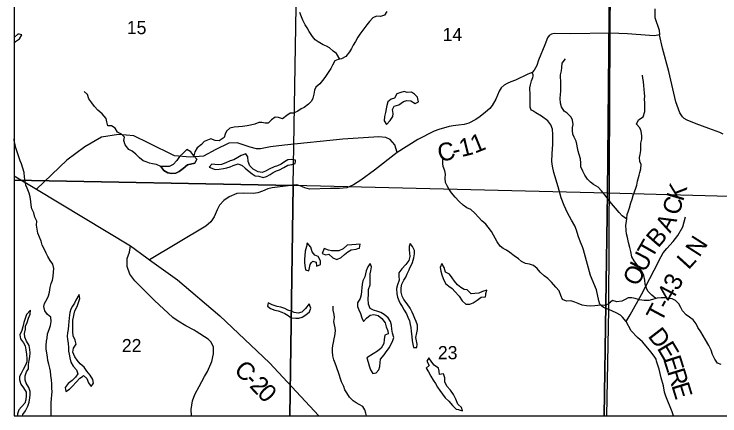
# Model space of a CAD drawing. Extents: x -452339 to 6403467, y -1 to 1814750.
# Drawn here: x -75201 to -63350, y 1547986 to 1554727 of the extents above; entities that cross this region are included whole.
import ezdxf

# ---------------------------------------------------------------- set-up
doc = ezdxf.new("R2010")
doc.units = 0
for name, color, linetype in [('Default', 7, 'Continuous'), ('GM_X_County', 7, 'Continuous'), ('GM_X_County_ROW', 7, 'Continuous'), ('GM_X_Major_Lake', 7, 'Continuous'), ('GM_X_Major_Lake_Text', 7, 'Continuous'), ('GM_X_Major_River_Text', 7, 'Continuous'), ('GM_X_Section', 7, 'Continuous'), ('GM_X_Section_Text', 7, 'Continuous'), ('GM_X_Township_Road_Text', 7, 'Continuous'), ('GM_X_Unincorporated_Location', 7, 'Continuous')]:
    doc.layers.add(name, color=color, linetype=linetype)

msp = doc.modelspace()

# ---------------------------------------------------------------- linework, layer by layer
at = {"layer": 'Default'}
msp.add_lwpolyline([(-68770, 1552404), (-68810, 1552533), (-68887, 1552621), (-68957, 1552656), (-69077, 1552667), (-69679, 1552627), (-70661, 1552529), (-70894, 1552499), (-71064, 1552465), (-71130, 1552465), (-71236, 1552494), (-71457, 1552569), (-71597, 1552563), (-71812, 1552458), (-72022, 1552346), (-72245, 1552325), (-72507, 1552350), (-72940, 1552559), (-73190, 1552686), (-73448, 1552709), (-73731, 1552664), (-74015, 1552500), (-74314, 1552276), (-74826, 1551789)], dxfattribs=at)
at = {"layer": 'GM_X_County_ROW'}
for points in [[(-63293, 1552711), (-63353, 1552739), (-63537, 1552806), (-63750, 1552884), (-63900, 1552947), (-63952, 1552973), (-63980, 1553002), (-64023, 1553072), (-64090, 1553258), (-64209, 1553766), (-64311, 1554154), (-64363, 1554377)], [(-65303, 1549803), (-65305, 1549804), (-65338, 1549832), (-65365, 1549862), (-65383, 1549916), (-65420, 1550101), (-65525, 1550340), (-65642, 1550774), (-65658, 1550824), (-65693, 1550898), (-65728, 1551006), (-65760, 1551103), (-65787, 1551175), (-65839, 1551271), (-65906, 1551395), (-65967, 1551518), (-66014, 1551642), (-66063, 1551830), (-66139, 1552068), (-66162, 1552176), (-66170, 1552254), (-66165, 1552380), (-66156, 1552543), (-66153, 1552709), (-66158, 1552797), (-66187, 1552871), (-66237, 1552939), (-66344, 1553016), (-66438, 1553073), (-66492, 1553103), (-66516, 1553117), (-66526, 1553131), (-66534, 1553165), (-66534, 1553369), (-66539, 1553491), (-66531, 1553543), (-66516, 1553607), (-66490, 1553662), (-66484, 1553688), (-66484, 1553708), (-66502, 1553748)], [(-64921, 1549570), (-64855, 1549683), (-64665, 1550021), (-64454, 1550431), (-64334, 1550658), (-64302, 1550724), (-64241, 1550793), (-64134, 1550910), (-64056, 1551013), (-63973, 1551160), (-63927, 1551324)], [(-72004, 1548644), (-72003, 1548644), (-71956, 1548730), (-71880, 1548900), (-71854, 1549028), (-71854, 1549136), (-71892, 1549222), (-71943, 1549273), (-72143, 1549403), (-72177, 1549425), (-72316, 1549498), (-72444, 1549574), (-72537, 1549638), (-72843, 1549921), (-73174, 1550252), (-73257, 1550363), (-73305, 1550495), (-73302, 1550627), (-73265, 1550732), (-73249, 1550837)], [(-64127, 1547986), (-64153, 1548052), (-64257, 1548317), (-64280, 1548385), (-64296, 1548487), (-64335, 1548625), (-64370, 1548769), (-64415, 1548903), (-64422, 1548937), (-64444, 1548973), (-64506, 1549054), (-64651, 1549227), (-64734, 1549301), (-64839, 1549410), (-64921, 1549570), (-64984, 1549644), (-65018, 1549673), (-65093, 1549716), (-65216, 1549772), (-65260, 1549790), (-65303, 1549803)], [(-72225, 1547986), (-72226, 1548093), (-72207, 1548239), (-72165, 1548344), (-72096, 1548479), (-72004, 1548644)]]:
    msp.add_lwpolyline(points, dxfattribs=at)
at = {"layer": 'GM_X_Major_River_Text'}
for points in [[(-75118, 1554388), (-75137, 1554390), (-75201, 1554333)], [(-75201, 1554251), (-75176, 1554266), (-75112, 1554314), (-75069, 1554382), (-75118, 1554388)], [(-68422, 1553307), (-68428, 1553333), (-68478, 1553385), (-68530, 1553416), (-68600, 1553412), (-68650, 1553426), (-68710, 1553414), (-68772, 1553388), (-68815, 1553319), (-68871, 1553301), (-68927, 1553253), (-68941, 1553193), (-68953, 1553139), (-68967, 1553075), (-68982, 1553008), (-68990, 1552934), (-68948, 1552876)], [(-68948, 1552876), (-68888, 1552943), (-68841, 1553009), (-68837, 1553061), (-68847, 1553125), (-68817, 1553183), (-68743, 1553207), (-68663, 1553262), (-68607, 1553280), (-68537, 1553270), (-68465, 1553230), (-68411, 1553257), (-68422, 1553307)], [(-72182, 1552348), (-72231, 1552417), (-72300, 1552453), (-72365, 1552396), (-72423, 1552338), (-72466, 1552269), (-72530, 1552205), (-72595, 1552170), (-72740, 1552171)], [(-70476, 1552255), (-70474, 1552274), (-70544, 1552286), (-70604, 1552284), (-70659, 1552248), (-70719, 1552210), (-70779, 1552179), (-70835, 1552163), (-70917, 1552127), (-70979, 1552093), (-71035, 1552070), (-71105, 1552080), (-71185, 1552128), (-71245, 1552184), (-71271, 1552254), (-71277, 1552330), (-71310, 1552382), (-71388, 1552357), (-71447, 1552321), (-71511, 1552283), (-71573, 1552265), (-71647, 1552234), (-71717, 1552206), (-71773, 1552200), (-71829, 1552204), (-71879, 1552212), (-71927, 1552161)], [(-72740, 1552171), (-72685, 1552104), (-72619, 1552062), (-72553, 1552055), (-72483, 1552061), (-72431, 1552086), (-72362, 1552138), (-72288, 1552197), (-72167, 1552226), (-72135, 1552292), (-72182, 1552348)], [(-71927, 1552161), (-71823, 1552122), (-71757, 1552128), (-71687, 1552138), (-71629, 1552148), (-71575, 1552163), (-71521, 1552185), (-71437, 1552213), (-71369, 1552187), (-71319, 1552145), (-71253, 1552084), (-71201, 1552048), (-71151, 1552016), (-71091, 1552008), (-71017, 1551988), (-70965, 1552002), (-70903, 1552035), (-70851, 1552071), (-70797, 1552095), (-70745, 1552117), (-70671, 1552154), (-70603, 1552194), (-70535, 1552206), (-70481, 1552220), (-70476, 1552255)], [(-70280, 1550888), (-70293, 1550826), (-70311, 1550750), (-70321, 1550675), (-70325, 1550613), (-70325, 1550561), (-70318, 1550511), (-70306, 1550439), (-70254, 1550421), (-70240, 1550472), (-70232, 1550524), (-70205, 1550560)], [(-70205, 1550560), (-70187, 1550584), (-70131, 1550566), (-70122, 1550498), (-70059, 1550526), (-70057, 1550588), (-70095, 1550658), (-70149, 1550684), (-70199, 1550738), (-70217, 1550814), (-70280, 1550888)], [(-69431, 1550792), (-69404, 1550801), (-69390, 1550867), (-69458, 1550863), (-69528, 1550856), (-69606, 1550848), (-69675, 1550788), (-69749, 1550756), (-69803, 1550753), (-69871, 1550757), (-69923, 1550767), (-69995, 1550795)], [(-68554, 1550469), (-68535, 1550507), (-68513, 1550558), (-68487, 1550638), (-68478, 1550704), (-68480, 1550762), (-68512, 1550828), (-68548, 1550880), (-68570, 1550826), (-68568, 1550770), (-68560, 1550718), (-68554, 1550660), (-68573, 1550595), (-68623, 1550523), (-68691, 1550455), (-68743, 1550385), (-68742, 1550329), (-68736, 1550265), (-68762, 1550186), (-68782, 1550122), (-68774, 1550034), (-68761, 1549976), (-68743, 1549924), (-68717, 1549872), (-68685, 1549820), (-68651, 1549760), (-68613, 1549698), (-68590, 1549643), (-68562, 1549581), (-68548, 1549521), (-68540, 1549471), (-68532, 1549399), (-68522, 1549320), (-68515, 1549244), (-68497, 1549132)], [(-69995, 1550795), (-70031, 1550712), (-69969, 1550689), (-69915, 1550701), (-69851, 1550637), (-69781, 1550611), (-69707, 1550646), (-69651, 1550692), (-69597, 1550740), (-69541, 1550774), (-69458, 1550785), (-69431, 1550792)], [(-69252, 1550501), (-69263, 1550487), (-69287, 1550421), (-69298, 1550371), (-69314, 1550317), (-69346, 1550254), (-69358, 1550198), (-69364, 1550134), (-69367, 1550076), (-69373, 1550014), (-69393, 1549956), (-69435, 1549884), (-69437, 1549822), (-69410, 1549764), (-69382, 1549702), (-69364, 1549632), (-69336, 1549570), (-69284, 1549626), (-69220, 1549678), (-69160, 1549687), (-69086, 1549671), (-69024, 1549617), (-68972, 1549547), (-68956, 1549479), (-68928, 1549415), (-68919, 1549363), (-68975, 1549339), (-68985, 1549267), (-68993, 1549199), (-69037, 1549123), (-69101, 1549070), (-69170, 1549024), (-69278, 1548960)], [(-69278, 1548960), (-69254, 1548886), (-69238, 1548828), (-69218, 1548758), (-69179, 1548698), (-69119, 1548710), (-69074, 1548760), (-69062, 1548812), (-69056, 1548882), (-69048, 1548936), (-68986, 1549009), (-68955, 1549063), (-68899, 1549131), (-68875, 1549181), (-68847, 1549233), (-68827, 1549301), (-68848, 1549373), (-68858, 1549439), (-68864, 1549507), (-68880, 1549567), (-68922, 1549633), (-68990, 1549687), (-69041, 1549719), (-69093, 1549737), (-69167, 1549759), (-69221, 1549790), (-69251, 1549862), (-69255, 1549952), (-69249, 1550021), (-69250, 1550109), (-69224, 1550183), (-69220, 1550245), (-69220, 1550367), (-69213, 1550419), (-69199, 1550487), (-69221, 1550541), (-69252, 1550501)], [(-68497, 1549132), (-68437, 1549133), (-68431, 1549189), (-68447, 1549247), (-68456, 1549303), (-68438, 1549377), (-68426, 1549437), (-68430, 1549505), (-68452, 1549567), (-68474, 1549619), (-68495, 1549673), (-68517, 1549727), (-68551, 1549793), (-68603, 1549867), (-68659, 1549939), (-68687, 1549996), (-68704, 1550060), (-68704, 1550133), (-68688, 1550193), (-68656, 1550265), (-68624, 1550315), (-68601, 1550369), (-68569, 1550439), (-68554, 1550469)], [(-68017, 1550541), (-68047, 1550473), (-68037, 1550415), (-68017, 1550351), (-67999, 1550291), (-67956, 1550209), (-67902, 1550165), (-67848, 1550124), (-67800, 1550070), (-67730, 1549992), (-67678, 1549916), (-67618, 1549860), (-67550, 1549860), (-67494, 1549881), (-67428, 1549929), (-67356, 1549975), (-67284, 1549985), (-67282, 1550014)], [(-67282, 1550014), (-67280, 1550037), (-67266, 1550093), (-67336, 1550075), (-67400, 1550043), (-67466, 1550041), (-67524, 1550033), (-67592, 1550098), (-67644, 1550104), (-67700, 1550142), (-67756, 1550184), (-67807, 1550248), (-67845, 1550302), (-67891, 1550364), (-67955, 1550399), (-67979, 1550473), (-68017, 1550541)], [(-74108, 1550025), (-74165, 1549930), (-74187, 1549878), (-74218, 1549828), (-74248, 1549774), (-74265, 1549722), (-74275, 1549630), (-74280, 1549562), (-74286, 1549505), (-74295, 1549435), (-74305, 1549377), (-74309, 1549321), (-74304, 1549269), (-74296, 1549207), (-74289, 1549127), (-74285, 1549073), (-74277, 1549019), (-74266, 1548959), (-74248, 1548886), (-74207, 1548822), (-74151, 1548760), (-74130, 1548692), (-74172, 1548634), (-74228, 1548582), (-74295, 1548527), (-74341, 1548461), (-74330, 1548397), (-74272, 1548433), (-74221, 1548482), (-74159, 1548550), (-74096, 1548616), (-74055, 1548647)], [(-74055, 1548647), (-74034, 1548663), (-73982, 1548615), (-73952, 1548541), (-73907, 1548480), (-73868, 1548536), (-73878, 1548598), (-73925, 1548670), (-73979, 1548737), (-74023, 1548801), (-74092, 1548857), (-74142, 1548918), (-74182, 1548978), (-74215, 1549052), (-74205, 1549120), (-74158, 1549188), (-74178, 1549258), (-74209, 1549330), (-74213, 1549404), (-74216, 1549468), (-74216, 1549540), (-74213, 1549590), (-74205, 1549642), (-74193, 1549698), (-74180, 1549750), (-74142, 1549819), (-74119, 1549889), (-74099, 1549957), (-74108, 1550025)], [(-70934, 1549883), (-70948, 1549829), (-70898, 1549787), (-70824, 1549759), (-70766, 1549749), (-70704, 1549727), (-70654, 1549701), (-70600, 1549668), (-70573, 1549650)], [(-70573, 1549650), (-70544, 1549630), (-70470, 1549624), (-70418, 1549628), (-70366, 1549640), (-70300, 1549681), (-70242, 1549733), (-70218, 1549795), (-70246, 1549863), (-70310, 1549789), (-70368, 1549726), (-70430, 1549708), (-70500, 1549722), (-70550, 1549742), (-70604, 1549762), (-70656, 1549786), (-70722, 1549811), (-70784, 1549821), (-70866, 1549851), (-70934, 1549883)], [(-74925, 1549757), (-74992, 1549687), (-75016, 1549622), (-75037, 1549554), (-75053, 1549482), (-75074, 1549416), (-75103, 1549348), (-75095, 1549278), (-75041, 1549212), (-75016, 1549160), (-75002, 1549096), (-74993, 1549022), (-74989, 1548944), (-74990, 1548890), (-75008, 1548836), (-75050, 1548762), (-75085, 1548696), (-75109, 1548645), (-75110, 1548593), (-75088, 1548518), (-75043, 1548454), (-74999, 1548382), (-75001, 1548326), (-75004, 1548254), (-75022, 1548200), (-75075, 1548135), (-75123, 1548085), (-75146, 1548019), (-75146, 1547986)], [(-75058, 1547986), (-75052, 1548008), (-75007, 1548068), (-74969, 1548148), (-74946, 1548216), (-74936, 1548286), (-74933, 1548341), (-74933, 1548395), (-74952, 1548464), (-75000, 1548534), (-75016, 1548586), (-75017, 1548658), (-74991, 1548724), (-74960, 1548774), (-74958, 1548845), (-74949, 1548917), (-74937, 1548977), (-74932, 1549041), (-74936, 1549097), (-74949, 1549169), (-74993, 1549238), (-75023, 1549304), (-75026, 1549368), (-75012, 1549440), (-75009, 1549490), (-74983, 1549555), (-74960, 1549623), (-74932, 1549693), (-74925, 1549757)], [(-67740, 1548091), (-67728, 1548088), (-67674, 1548072), (-67690, 1548124), (-67750, 1548180), (-67785, 1548264), (-67825, 1548342), (-67873, 1548416), (-67935, 1548482), (-67969, 1548558), (-67968, 1548622), (-67990, 1548690), (-68060, 1548678), (-68064, 1548734), (-68076, 1548788), (-68150, 1548835), (-68186, 1548889), (-68235, 1548959), (-68272, 1548905), (-68233, 1548829), (-68284, 1548787)], [(-68284, 1548787), (-68244, 1548723), (-68204, 1548651), (-68163, 1548587), (-68127, 1548529), (-68091, 1548465), (-68053, 1548413), (-68009, 1548351), (-67963, 1548288), (-67903, 1548232), (-67842, 1548160), (-67780, 1548100), (-67740, 1548091)]]:
    msp.add_lwpolyline(points, dxfattribs=at)
at = {"layer": 'GM_X_Section'}
for points in [[(-64444, 1554816), (-64441, 1554672), (-64370, 1554460), (-64363, 1554377), (-64448, 1554362), (-64530, 1554371), (-64899, 1554399), (-65190, 1554407), (-65211, 1554407)], [(-65211, 1554407), (-65855, 1554399), (-66135, 1554402), (-66177, 1554392), (-66217, 1554368), (-66247, 1554330), (-66292, 1554214), (-66396, 1553957), (-66424, 1553863), (-66466, 1553787), (-66502, 1553748), (-66576, 1553718), (-66782, 1553620), (-66858, 1553590), (-66924, 1553564), (-66972, 1553533), (-67020, 1553489), (-67054, 1553437), (-67111, 1553299), (-67175, 1553195), (-67215, 1553144), (-67285, 1553080), (-67373, 1553012), (-67449, 1552958), (-67567, 1552900), (-67643, 1552873), (-67741, 1552863), (-67829, 1552855), (-67895, 1552839), (-68067, 1552791), (-68145, 1552763), (-68424, 1552624), (-68770, 1552404), (-69150, 1552108), (-69377, 1551940), (-69501, 1551863), (-69613, 1551815), (-69739, 1551803), (-69891, 1551803), (-70241, 1551792), (-70317, 1551812), (-70397, 1551848), (-70459, 1551862), (-70555, 1551852), (-70867, 1551815), (-70939, 1551795), (-71029, 1551759), (-71111, 1551729), (-71185, 1551717), (-71353, 1551722), (-71463, 1551716), (-71592, 1551660), (-71682, 1551598), (-71750, 1551519), (-71794, 1551441), (-71844, 1551325), (-71900, 1551239), (-71980, 1551169), (-72928, 1550606)], [(-75201, 1552016), (-74826, 1551789), (-73249, 1550837), (-72974, 1550639)], [(-72974, 1550639), (-72974, 1550639), (-72928, 1550606), (-72455, 1550267), (-71749, 1549667), (-70915, 1548873), (-70085, 1547986)]]:
    msp.add_lwpolyline(points, dxfattribs=at)
at = {"layer": 'GM_X_Section_Text'}
msp.add_lwpolyline([(-65017, 1563141), (-75201, 1563141), (-75201, 1547986), (-65250, 1547986), (-65216, 1549772), (-65190, 1554407), (-65173, 1556707), (-65039, 1562427)], close=True, dxfattribs=at)
at = {"layer": 'GM_X_Township_Road_Text'}
for points in [[(-68940, 1554773), (-68980, 1554710), (-69048, 1554690), (-69118, 1554692), (-69175, 1554666), (-69235, 1554603), (-69279, 1554545), (-69347, 1554459), (-69397, 1554393), (-69432, 1554340), (-69466, 1554270), (-69506, 1554206), (-69538, 1554150), (-69572, 1554094), (-69631, 1554017), (-69701, 1553977), (-69757, 1553967), (-69817, 1553945), (-69855, 1553872), (-69885, 1553816), (-69926, 1553746), (-69982, 1553666), (-70022, 1553613), (-70070, 1553559), (-70135, 1553503), (-70157, 1553453), (-70169, 1553385), (-70183, 1553315), (-70209, 1553264), (-70255, 1553214), (-70328, 1553162), (-70382, 1553136), (-70438, 1553101), (-70508, 1553067), (-70566, 1553063), (-70622, 1553025), (-70694, 1552972), (-70764, 1552994), (-70816, 1553000), (-70878, 1552956), (-70933, 1552900), (-70987, 1552897), (-71041, 1552911), (-71093, 1552911), (-71161, 1552879), (-71229, 1552866), (-71287, 1552852), (-71367, 1552842), (-71431, 1552836), (-71507, 1552829), (-71577, 1552815), (-71635, 1552763), (-71656, 1552713), (-71672, 1552657), (-71756, 1552600), (-71826, 1552608), (-71896, 1552632), (-72011, 1552588)], [(-69732, 1553971), (-69789, 1554065), (-69843, 1554105), (-69904, 1554163), (-69958, 1554188), (-70010, 1554212), (-70096, 1554260), (-70146, 1554296), (-70192, 1554354), (-70244, 1554436), (-70282, 1554496), (-70315, 1554550), (-70355, 1554626), (-70373, 1554680), (-70403, 1554756)], [(-64914, 1551289), (-64989, 1551341), (-65039, 1551400), (-65103, 1551472), (-65170, 1551548), (-65228, 1551622), (-65284, 1551692), (-65338, 1551764), (-65392, 1551824), (-65470, 1551869), (-65521, 1551905), (-65573, 1551959), (-65619, 1552025), (-65653, 1552091), (-65685, 1552167), (-65685, 1552227), (-65688, 1552297), (-65712, 1552369), (-65732, 1552425), (-65740, 1552483), (-65750, 1552545), (-65765, 1552597), (-65799, 1552661), (-65817, 1552715), (-65825, 1552773), (-65825, 1552823), (-65815, 1552875), (-65826, 1552945), (-65850, 1552999), (-65912, 1553065), (-65962, 1553101), (-66012, 1553171), (-66024, 1553231), (-66033, 1553313), (-66027, 1553377), (-66021, 1553435), (-66021, 1553605), (-66024, 1553661), (-66028, 1553711), (-66010, 1553774), (-66006, 1553830), (-66000, 1553902), (-65943, 1553978)], [(-64428, 1549953), (-64491, 1550013), (-64561, 1550079), (-64582, 1550131), (-64602, 1550197), (-64612, 1550263), (-64626, 1550339), (-64654, 1550405), (-64701, 1550469), (-64743, 1550525), (-64787, 1550585), (-64831, 1550656), (-64847, 1550742), (-64864, 1550812), (-64886, 1550894), (-64902, 1550977), (-64916, 1551039), (-64926, 1551099), (-64929, 1551183), (-64917, 1551249), (-64913, 1551299), (-64905, 1551363), (-64885, 1551427), (-64868, 1551477), (-64844, 1551559), (-64824, 1551623), (-64804, 1551682), (-64782, 1551744), (-64759, 1551806), (-64743, 1551856), (-64735, 1551924), (-64707, 1552022), (-64695, 1552072), (-64678, 1552130), (-64672, 1552201), (-64696, 1552254), (-64702, 1552319), (-64690, 1552373), (-64676, 1552439), (-64677, 1552493), (-64675, 1552563), (-64663, 1552627), (-64663, 1552685), (-64671, 1552761), (-64696, 1552817), (-64752, 1552883), (-64714, 1552951), (-64636, 1553006), (-64613, 1553094), (-64613, 1553156), (-64611, 1553238), (-64615, 1553298), (-64613, 1553352), (-64615, 1553402), (-64622, 1553466), (-64626, 1553522), (-64630, 1553594), (-64642, 1553650), (-64650, 1553702)], [(-72011, 1552588), (-72057, 1552539), (-72125, 1552481), (-72164, 1552414), (-72182, 1552348), (-72135, 1552292), (-72167, 1552226), (-72219, 1552216), (-72288, 1552197), (-72362, 1552138), (-72431, 1552086), (-72483, 1552061), (-72553, 1552055), (-72619, 1552062), (-72685, 1552104), (-72740, 1552171), (-72810, 1552201), (-72876, 1552216), (-72930, 1552228), (-72984, 1552247), (-73034, 1552265), (-73098, 1552314), (-73159, 1552376), (-73221, 1552430), (-73275, 1552457), (-73334, 1552531), (-73358, 1552609), (-73345, 1552661), (-73397, 1552712), (-73465, 1552748), (-73502, 1552812), (-73564, 1552851), (-73630, 1552855), (-73643, 1552917), (-73657, 1552976), (-73722, 1553054), (-73794, 1553113), (-73849, 1553175), (-73895, 1553241), (-73945, 1553306), (-73968, 1553376), (-74024, 1553430)], [(-74655, 1549237), (-74647, 1549291), (-74638, 1549362), (-74614, 1549434), (-74589, 1549504), (-74577, 1549570), (-74584, 1549642), (-74642, 1549686), (-74683, 1549747), (-74703, 1549823), (-74688, 1549874), (-74648, 1549950), (-74625, 1550002), (-74609, 1550062), (-74594, 1550140), (-74576, 1550207), (-74557, 1550261), (-74543, 1550325), (-74538, 1550395), (-74532, 1550457), (-74553, 1550531), (-74593, 1550591), (-74636, 1550659), (-74662, 1550714), (-74693, 1550780), (-74731, 1550848), (-74744, 1550916), (-74776, 1550982), (-74803, 1551049), (-74813, 1551117), (-74824, 1551187), (-74822, 1551253), (-74851, 1551319), (-74869, 1551391), (-74904, 1551461), (-74912, 1551521), (-74923, 1551585), (-74931, 1551659), (-74948, 1551721), (-74983, 1551807), (-75005, 1551858), (-75028, 1551990), (-75033, 1552070), (-75053, 1552142), (-75076, 1552214), (-75100, 1552268), (-75129, 1552348), (-75147, 1552414), (-75170, 1552482), (-75184, 1552534), (-75199, 1552610), (-75201, 1552633)], [(-64007, 1549805), (-64037, 1549863), (-64097, 1549924), (-64149, 1549948), (-64203, 1549956), (-64267, 1549968), (-64335, 1549968), (-64401, 1549961), (-64479, 1549937), (-64545, 1549923), (-64623, 1549921), (-64697, 1549934), (-64775, 1549958), (-64827, 1549968), (-64891, 1549964), (-64943, 1549941), (-64995, 1549913), (-65079, 1549901), (-65151, 1549921), (-65225, 1549862), (-65280, 1549836), (-65334, 1549846), (-65398, 1549838), (-65452, 1549834), (-65520, 1549827), (-65590, 1549833), (-65660, 1549843), (-65732, 1549871), (-65784, 1549896), (-65852, 1549914), (-65924, 1549908), (-65990, 1549940), (-66021, 1550006), (-66049, 1550084), (-66103, 1550144), (-66175, 1550229), (-66241, 1550289), (-66299, 1550335), (-66370, 1550395), (-66420, 1550461), (-66478, 1550507), (-66548, 1550530), (-66614, 1550544), (-66680, 1550578), (-66732, 1550622), (-66802, 1550672), (-66876, 1550725), (-66933, 1550765), (-66991, 1550793), (-67041, 1550833), (-67087, 1550907), (-67121, 1550965), (-67151, 1551017), (-67187, 1551079), (-67240, 1551151), (-67280, 1551202), (-67350, 1551256), (-67402, 1551318), (-67464, 1551386), (-67534, 1551446), (-67600, 1551478), (-67662, 1551519), (-67727, 1551581), (-67797, 1551657), (-67855, 1551731), (-67899, 1551793), (-67931, 1551845), (-67958, 1551903), (-67962, 1551975), (-67958, 1552043), (-67968, 1552099), (-67996, 1552169), (-68004, 1552221), (-68003, 1552285)], [(-69283, 1547986), (-69295, 1548031), (-69314, 1548087), (-69346, 1548143), (-69406, 1548179), (-69456, 1548202), (-69508, 1548238), (-69568, 1548302), (-69614, 1548370), (-69646, 1548422), (-69665, 1548478), (-69705, 1548556), (-69723, 1548608), (-69745, 1548682), (-69789, 1548806), (-69812, 1548870), (-69830, 1548926), (-69848, 1548992), (-69856, 1549064), (-69852, 1549114), (-69847, 1549164), (-69839, 1549216), (-69827, 1549280), (-69815, 1549330), (-69805, 1549412), (-69809, 1549462), (-69822, 1549512), (-69830, 1549572), (-69820, 1549638), (-69824, 1549688), (-69844, 1549760), (-69844, 1549824)], [(-63330, 1548846), (-63392, 1548872), (-63436, 1548940), (-63475, 1549016), (-63497, 1549088), (-63537, 1549164), (-63589, 1549260), (-63630, 1549327), (-63672, 1549397), (-63718, 1549467), (-63748, 1549531), (-63798, 1549599), (-63862, 1549643), (-63916, 1549681), (-63975, 1549747), (-64007, 1549805)], [(-74580, 1547986), (-74579, 1548047), (-74580, 1548103), (-74578, 1548155), (-74576, 1548205), (-74571, 1548279), (-74565, 1548333), (-74562, 1548392), (-74566, 1548446), (-74567, 1548526), (-74575, 1548590), (-74582, 1548662), (-74591, 1548734), (-74603, 1548789), (-74620, 1548851), (-74636, 1548917), (-74640, 1548971), (-74653, 1549045), (-74663, 1549103), (-74664, 1549169), (-74655, 1549237)]]:
    msp.add_lwpolyline(points, dxfattribs=at)
at = {"layer": 'GM_X_Unincorporated_Location'}
for points in [[(-75201, 1557273), (-75201, 1551940), (-70514, 1551852), (-70427, 1557185)], [(-70427, 1557185), (-65186, 1557097), (-65239, 1551725), (-70514, 1551852)], [(-65186, 1557097), (-59845, 1556965), (-59852, 1556683), (-59917, 1551576), (-65239, 1551725)], [(-75201, 1551940), (-75201, 1547986), (-70573, 1547986), (-70514, 1551852)], [(-70573, 1547986), (-65292, 1547986), (-65239, 1551725), (-70514, 1551852)], [(-65292, 1547986), (-59964, 1547986), (-59917, 1551388), (-59917, 1551576), (-65239, 1551725)]]:
    msp.add_lwpolyline(points, close=True, dxfattribs=at)

# ---------------------------------------------------------------- texts
at = {"layer": 'GM_X_County'}
for s, rotation, p in [('1', 22.0074, (-67465, 1552385)), ('1', 13.7803, (-67689, 1552327)), ('C', 13.1473, (-68053, 1552242)), ('-', 13.2521, (-67812, 1552298)), ('C', 315.8418, (-71525, 1548735)), ('-', 314.9117, (-71349, 1548565)), ('2', 314.2567, (-71263, 1548478)), ('0', 313.7672, (-71134, 1548346))]:
    msp.add_text(s, height=300, rotation=rotation, dxfattribs=at).set_placement(p)
at = {"layer": 'GM_X_Major_Lake'}
for s, p in [('15', (-73308, 1554391)), ('14', (-68006, 1554274)), ('22', (-73392, 1549055)), ('23', (-68085, 1548936))]:
    msp.add_text(s, height=220.8, rotation=0, dxfattribs=at).set_placement(p)
at = {"layer": 'GM_X_Major_Lake_Text'}
for s, rotation, p in [('K', 73.337, (-63969, 1551573)), ('C', 73.9544, (-64037, 1551337)), ('A', 62.5951, (-64183, 1551042)), ('B', 48.994, (-64388, 1550792)), ('T', 60.1424, (-64491, 1550610)), ('N', 57.4057, (-63695, 1550635)), ('U', 62.736, (-64610, 1550379)), ('L', 47.7952, (-63878, 1550426)), ('O', 62.8012, (-64731, 1550144)), ('T-43', 62.0054, (-64336, 1549540)), ('D', 307.8127, (-64570, 1549321)), ('E', 300.6279, (-64413, 1549121)), ('E', 287.5432, (-64307, 1548945)), ('R', 287.0981, (-64239, 1548731)), ('E', 287.0904, (-64167, 1548496))]:
    msp.add_text(s, height=300, rotation=rotation, dxfattribs=at).set_placement(p)

doc.saveas('drawing.dxf')
